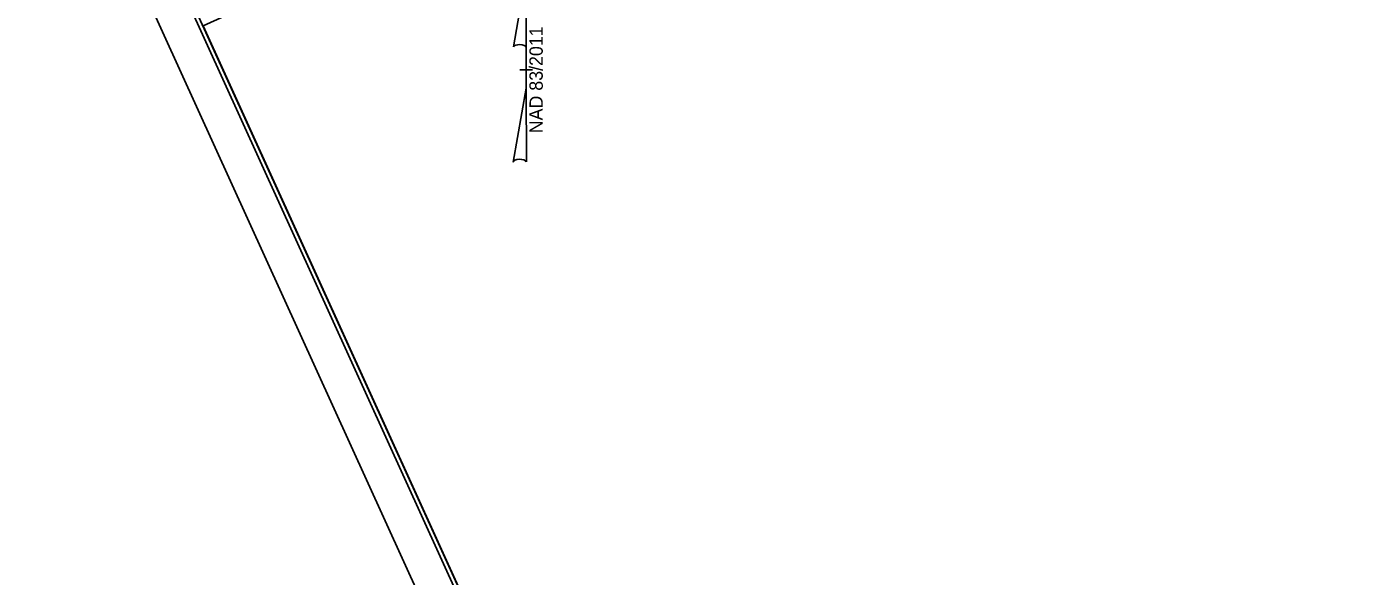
# Model space of a CAD drawing. Extents: x 2097304 to 2099003, y 683920 to 685908.
# Drawn here: x 2097304 to 2098154, y 684914 to 685265 of the extents above; entities that cross this region are included whole.
import ezdxf

# ---------------------------------------------------------------- set-up
doc = ezdxf.new("R2010")
doc.units = 0
for name, color, linetype in [('Prop North Arrow NAD83 for Plan Sheets CELL', 7, 'Continuous'), ('Sheet Layout Plan Border', 7, 'Continuous'), ('Sheet Plot Border Inside CELL', 7, 'Continuous'), ('Sheet Plot Border Outside CELL', 7, 'Continuous'), ('Sheet Profile CELL', 7, 'Continuous')]:
    doc.layers.add(name, color=color, linetype=linetype)

msp = doc.modelspace()

# ---------------------------------------------------------------- linework, layer by layer
at = {"layer": 'Prop North Arrow NAD83 for Plan Sheets CELL'}
for p, q in [((2097615.03, 685252.08), (2097623.23, 685298.43)), ((2097623.28, 685298.43), (2097623.28, 685250.63)), ((2097623.28, 685225.83), (2097623.28, 685252.03)), ((2097623.28, 685250.63), (2097623.28, 685251.98)), ((2097619.28, 685237.43), (2097619.23, 685237.43)), ((2097622.83, 685237.43), (2097619.28, 685237.43)), ((2097619.33, 685237.43), (2097627.33, 685237.43)), ((2097623.28, 685225.83), (2097614.93, 685178.58)), ((2097623.33, 685178.78), (2097623.28, 685225.83))]:
    msp.add_line(p, q, dxfattribs=at)
for centre, start_param, end_param in [((2097619.16, 685251.59), 0.216388, 2.908219), ((2097619.16, 685178.42), 0.201328, 3.141593)]:
    msp.add_ellipse(centre, major_axis=(4.23, -0.03), ratio=0.461098, start_param=start_param, end_param=end_param, dxfattribs=at)
at = {"layer": 'Sheet Layout Plan Border'}
msp.add_lwpolyline([(2098911.14, 684517.12), (2097955.44, 684082.23), (2097417.03, 685265.44), (2097587.51, 685343.02), (2097536.86, 685454.34), (2098323.16, 685809.28)], close=True, dxfattribs=at)
at = {"layer": 'Sheet Plot Border Inside CELL'}
msp.add_lwpolyline([(2098977.25, 684378), (2098287.02, 685894.84), (2097326.67, 685457.85), (2098016.9, 683941)], close=True, dxfattribs=at)
at = {"layer": 'Sheet Plot Border Outside CELL'}
msp.add_lwpolyline([(2099003.07, 684375.47), (2098305.59, 685908.24), (2097304.38, 685452.65), (2098001.85, 683919.87)], close=True, dxfattribs=at)
at = {"layer": 'Sheet Profile CELL'}
msp.add_lwpolyline([(2097334.17, 685447.53), (2097955.44, 684082.23), (2098911.14, 684517.12), (2098289.88, 685882.41)], close=True, dxfattribs=at)

# ---------------------------------------------------------------- texts
at = {"layer": 'Prop North Arrow NAD83 for Plan Sheets CELL'}
msp.add_text('NAD 83/2011', height=8.5, rotation=90, dxfattribs=at).set_placement((2097633.8, 685196.96))

doc.saveas('drawing.dxf')
